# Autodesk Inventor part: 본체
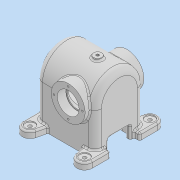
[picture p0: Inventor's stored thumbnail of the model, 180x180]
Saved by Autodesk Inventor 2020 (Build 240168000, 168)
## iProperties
Created: 2024-09
Part Number: 본체
Material: 일반
Document SubType Name: Modeling
Designer: oem
Density: 1 g/cm^3
Appearance: 기본값
Mass: 515.063 g
Surface Area: 1154.22 cm^2
Volume: 515.063 cm^3
Author: oem
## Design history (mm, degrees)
sketch "스케치1"
  geometry: L1 (0, 45)-(-76, 45); L2 (-76, 45)-(-76, -45); L3 (-76, -45)-(0, -45); L4 (0, -45)-(0, 45); A1 r 45 centre (0, 0) between (0, -45) and (0, 45); 1 further point
  constraints: 8 end point, 2 parallel, 2 point on circle, 2 tangent, 1 centre point, 1 coincident, 1 horizontal, 1 perpendicular
  dimensions: "d0" = 90 diameter of A1; "d1" = 76 distance between parallel lines of L2 L4
extrude "돌출1" new body sketch "스케치1" stored distance "d2" = 108; taper "d3" = 0 deg
feature "쉘1" dims "d5" = 9
node "작업 평면2"
sketch "스케치3"
  geometry: L1 (-22, -105)-(-22, -72); L2 (-22, -72)-(14, -72); L3 (14, -72)-(5.64, -108.154); L4 (106, -105)-(106, -72); L5 (106, -72)-(70, -72); L6 (70, -72)-(78.36, -108.154); L7 (-12, -90)-(96, -90) reference; L8 (-12, 0)-(-12, -90) reference; A1 r 14 centre (-8, -105) between (-22, -105) and (5.64, -108.154); A2 r 14 centre (92, -105) between (106, -105) and (78.36, -108.154); 3 further points
  constraints: 12 end point, 4 point on circle, 4 tangent, 2 centre point, 2 perpendicular, 2 vertical, 1 equal radius, 1 horizontal alignment, 1 midpoint
  dimensions: "d12" = 36 distance from line of L2.end L1; "d18" = 14 distance from line of A1.centre L1; "d19" = 100 distance of A2.centre A1.centre; "d20" = 128 distance between parallel lines of L4 L1; "d22" = 36 distance of L4.end L5.end; "d70" = 60 vertical distance of point (-12, -45) A1.centre; "d71" = 10 distance between parallel lines of L8 L1; "d72" = 18 distance between parallel lines of L2 L7
sketch "스케치14"
  geometry: L1 (-45, 0)-(-45, -76) reference; L2 (-45, -36)-(45, -36); L3 (-45, -45)-(45, -45); L4 (45, -76)-(45, 0) reference; L5 (-45, -36)-(-45, -45); L6 (45, -36)-(45, -45); L7 (-89.6, 0)-(89.6, 0) reference; 3 further points
  constraints: 8 end point, 4 point on line, 2 horizontal, 1 collinear, 1 parallel
  dimensions: "d67" = 45 distance from line of L3 point (0, 0); "d68" = 9 distance between parallel lines of L3 L2
revolve "회전2" sketch "스케치14" stored, may be unused: angle "d69" = 90 deg
extrude "돌출10" join sketch "스케치3" distance "d73" = 12; taper "d74" = 0 deg
node "작업 평면3"
sketch "스케치16"
  geometry: C1 r 28.5 at (0, 0); A1 r 45 centre (0, 0) between (45, 0) and (-45, 0) reference
  constraints: 1 centre point, 1 coincident
  dimensions: "d77" = 57 diameter of C1
extrude "돌출11" join sketch "스케치16" distance "d78" = 6; taper "d79" = 0 deg
sketch "스케치17"
  geometry: C1 r 28.5 at (0, 0) reference; C2 r 16.5 at (0, 0)
  constraints: 1 centre point, 1 coincident
  dimensions: "d80" = 33 diameter of C2
extrude "돌출12" cut sketch "스케치17" distance "d81" = 72; taper "d82" = 0 deg
sketch "스케치18"
  geometry: C1 r 16.5 at (0, 0) reference; 1 further point
  constraints: 1 vertical alignment
  dimensions: "d83" = 23 distance of C1.centre point (0, 23)
fillet "모깎기2" dims "d94" = 12
sketch "스케치19"
  geometry: L1 (-4, -1.5)-(-4, 55.5) reference; C1 r 7.5 at (-78, 27); 1 further point
  constraints: 1 centre point, 1 horizontal alignment
  dimensions: "d95" = 15 diameter of C1; "d96" = 74 distance from line of C1.centre L1
extrude "돌출13" join sketch "스케치19" stored distance "d97" = 72; taper "d98" = 0 deg
sketch "스케치20"
  geometry: C1 r 7.5 at (0, 0) reference; 2 further points
  constraints: 1 coincident
hole "구멍4" sketch "스케치20" at (0, 0) diameter "d99" = 5.1881; stored, may be unused: countersink angle "d103" = 60 deg, drill point angle "d105" = 118 deg; dims "d100" = 12, "d101" = 4.25, "d102" = 2, "d104" = 27.75
node "작업 평면4"
sketch "스케치21"
  geometry: L1 (42, 0)-(-42, 0) reference; L2 (60, -28.5)-(60, 28.5) reference; C1 r 31 at (-14, 0); 1 further point
  constraints: 1 centre point, 1 point on line
  dimensions: "d107" = 62 diameter of C1; "d108" = 74 distance from line of C1.centre L2
extrude "돌출14" join sketch "스케치21" stored distance "d109" = 72; taper "d110" = 0 deg
sketch "스케치22"
  geometry: C1 r 31 at (0, 0) reference; C2 r 20 at (0, 0); 1 further point
  constraints: 1 centre point, 1 coincident
  dimensions: "d111" = 40 diameter of C2
extrude "돌출15" cut sketch "스케치22" distance "d112" = 16; taper "d113" = 0 deg
sketch "스케치23"
  geometry: C1 r 20 at (0, 0) reference; 2 further points
  constraints: 1 vertical alignment
  dimensions: "d114" = 26 distance of C1.centre point (0, 26)
hole "구멍5" sketch "스케치23" at (0, 26) diameter "d115" = 3.242; stored, may be unused: countersink angle "d119" = 60 deg, drill point angle "d121" = 118 deg; dims "d116" = 8, "d117" = 4.25, "d118" = 2, "d120" = 10
sketch "스케치24"
  geometry: C1 r 20 at (0, 0) reference; C2 r 17.5 at (0, 0); 1 further point
  constraints: 1 centre point, 1 coincident
  dimensions: "d125" = 35 diameter of C2
extrude "돌출16" cut sketch "스케치24" distance "d126" = 44; taper "d127" = 0 deg
fillet "모깎기3" dims "d128" = 0.3
fillet "모깎기4" dims "d129" = 0.3
sketch "스케치25"
  geometry: L1 (-27, -76)-(27, -76) reference; A1 r 33 centre (0, 0) between (33, 0) and (-33, 0) reference; 1 further point
  constraints: 1 vertical alignment, 1 other
  dimensions: "d130" = 35 distance from line of point (0, -41) L1
feature "엠보싱1" sketch "스케치25" dims "d12" = 36, "d18" = 14, "d19" = 100, "d20" = 128, "d22" = 36, "d70" = 60, "d71" = 10, "d72" = 18, "d131" = 0.5, "d132" = 0
sketch "스케치26"
  geometry: A1 r 14 centre (92, 105) between (106, 105) and (78.36, 108.154) reference; A2 r 14 centre (92, -15) between (78.36, -18.154) and (106, -15) reference; A3 r 14 centre (-8, -15) between (-22, -15) and (5.64, -18.154) reference; 1 further point
hole "구멍6" sketch "스케치26" diameter "d133" = 6.6; stored, may be unused: countersink angle "d137" = 60 deg, drill point angle "d139" = 118 deg; dims "d134" = 8, "d135" = 18, "d136" = 2, "d138" = 10
hole "구멍7" sketch "스케치26" diameter "d140" = 6.6; stored, may be unused: countersink angle "d144" = 60 deg, drill point angle "d146" = 118 deg; dims "d141" = 8, "d142" = 18, "d143" = 2, "d145" = 10
sketch "스케치27"
  geometry: A1 r 14 centre (-8, 105) between (5.64, 108.154) and (-22, 105) reference; 1 further point
hole "구멍8" sketch "스케치27" at (-8, 105) diameter "d147" = 6.6; stored, may be unused: countersink angle "d151" = 60 deg, drill point angle "d153" = 118 deg; dims "d148" = 8, "d149" = 18, "d150" = 2, "d152" = 10
fillet "모깎기5" dims "d154" = 3
fillet "모깎기6" dims "d155" = 3
fillet "모깎기7" dims "d156" = 3
fillet "모깎기8" dims "d157" = 3
sketch "스케치28"
  geometry: L1 (20, -99)-(-20, -99); L2 (-20, -99)-(-20, -53); L3 (-20, -53)-(20, -53); L4 (20, -53)-(20, -99); L5 (27, -76)-(-27, -76) reference; L6 (20, -99)-(-20, -53); L7 (-20, -99)-(20, -53); 1 further point
  constraints: 12 end point, 3 midpoint, 2 parallel, 1 horizontal, 1 perpendicular
  dimensions: "d158" = 40 distance of L2.end L3.end; "d159" = 46 distance of L1.end L2.end
extrude "돌출17" cut sketch "스케치28" extent not by distance; stored distance "d160" = 0; taper "d161" = 0 deg
fillet "모깎기9" dims "d162" = 3
fillet "모깎기10" dims "d163" = 3
fillet "모깎기12" dims "d165" = 3
fillet "모깎기13" dims "d166" = 3
fillet "모깎기14" dims "d167" = 3
fillet "모깎기15" dims "d168" = 3
fillet "모깎기16" dims "d169" = 3
fillet "모깎기17" dims "d170" = 3
fillet "모깎기18" dims "d171" = 3
hole "구멍9" sketch "스케치18" diameter "d172" = 3.242; stored, may be unused: countersink angle "d176" = 82 deg, drill point angle "d178" = 118 deg; dims "d173" = 8, "d174" = 3.023, "d175" = 2, "d177" = 10
chamfer "모따기1" distance "d182" = 1; stored, may be unused: second distance "d183" = 2, angle "d184" = 45 deg
fillet "모깎기19" dims "d185" = 3
node "솔리드1"
mirror "미러2"
mirror "미러3"
pattern_circular "원형 패턴3" dims angle "d123" = 360 deg
mirror "미러4"
pattern_circular "원형 패턴4" dims angle "d180" = 360 deg
feature "A9D066F2-1C7D-4E18-AEED-F7BC21143FA4" dims "d133" = 6.6, "d134" = 8, "d135" = 18, "d136" = 2, "d137" = 60 deg, "d138" = 10, "d139" = 118 deg
other parameters: "d75" = -125, "d106" = -54
